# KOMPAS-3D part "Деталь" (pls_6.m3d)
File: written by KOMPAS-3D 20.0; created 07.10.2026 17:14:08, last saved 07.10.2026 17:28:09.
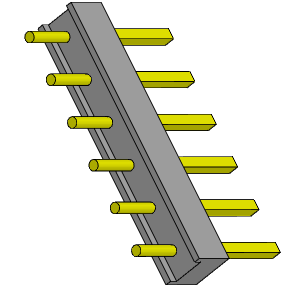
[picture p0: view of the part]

Document properties: Полное имя файла: D:\myProjects\Progect_esp32\box_compas\pls_6.m3d

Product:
- Part/product: Деталь
    Масса: 0.00078211

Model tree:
1. Эскиз:1
2. Элемент выдавливания:1
     Расстояние 1 = 2.5
3. Эскиз:2  (with: Элемент выдавливания:1)
4. Элемент выдавливания:2
     Расстояние 1 = 6
5. Массив по сетке:1  (with: Элемент выдавливания:2, Эскиз:2)  (6 pattern instances)
     Шаг 1 = 2.54; Угол раствора = 90
6. Эскиз:3  (with: Элемент выдавливания:1)
7. Элемент выдавливания:3
     Расстояние 1 = 3
8. Массив по сетке:2  (with: Элемент выдавливания:3, Эскиз:3)  (6 pattern instances)
     Шаг 1 = 2.54; Угол раствора = 90; Геометрический массив = 128
9. Эскиз:4  (with: Элемент выдавливания:1)
10. Элемент выдавливания:4
     Расстояние 2 = 15.24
